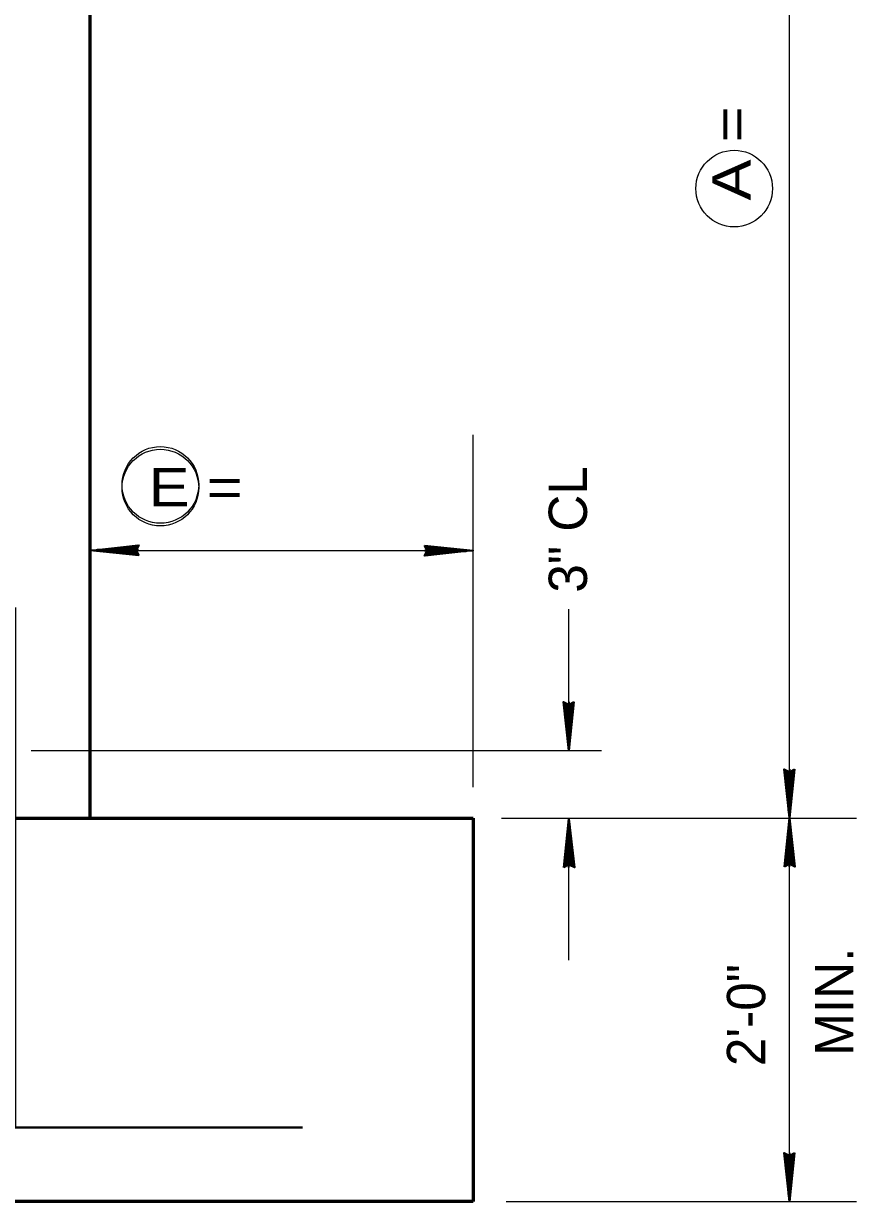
# Model space of a CAD drawing. Extents: x 4.49 to 7.69, y 0.28 to 2.27.
# Drawn here: x 6.09 to 6.2711, y 0.6015 to 0.8575 of the extents above; entities that cross this region are included whole.
import ezdxf

# ---------------------------------------------------------------- set-up
doc = ezdxf.new("R2010")
doc.units = 0
doc.header["$LTSCALE"] = 0.0033
doc.layers.add('1', color=7, linetype='Continuous', lineweight=35)

msp = doc.modelspace()

# ---------------------------------------------------------------- linework, layer by layer
at = {"layer": '1', "lineweight": 13}
for p, q in [((6.2565, 0.602333), (6.2565, 1.018083)), ((6.18775, 0.691583), (6.18775, 0.768167)), ((6.106, 0.743), (6.18775, 0.743)), ((6.208583, 0.709417), (6.208583, 0.73025)), ((6.091667, 0.6995), (6.215667, 0.6995)), ((6.193917, 0.684833), (6.271083, 0.684833)), ((6.208583, 0.653917), (6.208583, 0.67475)), ((6.140333, 0.6015), (6.182333, 0.6015)), ((6.194917, 0.6015), (6.271083, 0.6015))]:
    msp.add_line(p, q, dxfattribs=at)
at = {"layer": '1'}
for p, q in [((6.115083, 0.743), (6.1045, 0.743)), ((6.114833, 0.742167), (6.107, 0.743167)), ((6.114833, 0.742167), (6.107, 0.743)), ((6.114833, 0.742), (6.107, 0.742917)), ((6.114833, 0.742), (6.107, 0.742917)), ((6.114833, 0.742083), (6.107, 0.742917)), ((6.114833, 0.744083), (6.1075, 0.74325)), ((6.114833, 0.743917), (6.1075, 0.743167)), ((6.114833, 0.743833), (6.1075, 0.743)), ((6.114917, 0.743667), (6.107583, 0.742917)), ((6.177167, 0.743), (6.18775, 0.743)), ((6.177333, 0.742333), (6.184667, 0.743083)), ((6.177417, 0.744), (6.18525, 0.743083)), ((6.177417, 0.744), (6.18525, 0.743083)), ((6.177417, 0.743917), (6.18525, 0.743083)), ((6.177417, 0.743833), (6.18525, 0.743)), ((6.177417, 0.743833), (6.18525, 0.742833)), ((6.177417, 0.742167), (6.18475, 0.743)), ((6.177417, 0.742083), (6.18475, 0.742833)), ((6.177417, 0.741917), (6.18475, 0.74275)), ((6.2075, 0.709833), (6.208333, 0.7025)), ((6.207667, 0.709833), (6.208417, 0.7025)), ((6.20775, 0.709833), (6.208583, 0.7025)), ((6.207917, 0.709917), (6.208667, 0.702583)), ((6.209417, 0.709833), (6.208417, 0.702)), ((6.208583, 0.710083), (6.208583, 0.6995)), ((6.209417, 0.709833), (6.208583, 0.702)), ((6.209583, 0.709833), (6.208667, 0.702)), ((6.209583, 0.709833), (6.208667, 0.702)), ((6.2095, 0.709833), (6.208667, 0.702)), ((6.255417, 0.69525), (6.25625, 0.687917)), ((6.255583, 0.69525), (6.256333, 0.687917)), ((6.255667, 0.69525), (6.2565, 0.687917)), ((6.255833, 0.695333), (6.256583, 0.688)), ((6.257333, 0.69525), (6.256333, 0.687417)), ((6.2565, 0.6955), (6.2565, 0.684917)), ((6.257333, 0.69525), (6.2565, 0.687417)), ((6.2575, 0.69525), (6.256583, 0.687417)), ((6.2575, 0.69525), (6.256583, 0.687417)), ((6.257417, 0.69525), (6.256583, 0.687417)), ((6.208583, 0.674083), (6.208583, 0.684667)), ((6.2565, 0.67425), (6.2565, 0.684833)), ((6.207583, 0.674333), (6.2085, 0.682167)), ((6.207583, 0.674333), (6.2085, 0.682167)), ((6.207667, 0.674333), (6.2085, 0.682167)), ((6.20775, 0.674333), (6.208583, 0.682167)), ((6.20775, 0.674333), (6.20875, 0.682167)), ((6.20925, 0.67425), (6.2085, 0.681583)), ((6.209417, 0.674333), (6.208583, 0.681667)), ((6.2095, 0.674333), (6.20875, 0.681667)), ((6.209667, 0.674333), (6.208833, 0.681667)), ((6.2555, 0.6745), (6.256417, 0.682333)), ((6.2555, 0.6745), (6.256417, 0.682333)), ((6.255583, 0.6745), (6.256417, 0.682333)), ((6.255667, 0.6745), (6.2565, 0.682333)), ((6.255667, 0.6745), (6.256667, 0.682333)), ((6.257167, 0.674417), (6.256417, 0.68175)), ((6.257333, 0.6745), (6.2565, 0.681833)), ((6.257417, 0.6745), (6.256667, 0.681833)), ((6.257583, 0.6745), (6.25675, 0.681833)), ((6.2565, 0.612083), (6.2565, 0.6015)), ((6.255417, 0.611833), (6.25625, 0.6045)), ((6.255583, 0.611833), (6.256333, 0.6045)), ((6.255667, 0.611833), (6.2565, 0.6045)), ((6.255833, 0.611917), (6.256583, 0.604583)), ((6.257333, 0.611833), (6.256333, 0.604)), ((6.257333, 0.611833), (6.2565, 0.604)), ((6.2575, 0.611833), (6.256583, 0.604)), ((6.2575, 0.611833), (6.256583, 0.604)), ((6.257417, 0.611833), (6.256583, 0.604))]:
    msp.add_line(p, q, dxfattribs=at)
at = {"layer": '1', "lineweight": 60}
for p, q in [((6.18775, 0.684833), (6.18775, 0.6015)), ((6.18775, 0.6015), (5.854417, 0.6015))]:
    msp.add_line(p, q, dxfattribs=at)
for points in [[(5.854417, 0.684833), (5.93775, 0.684833), (5.93775, 1.018167), (6.104417, 1.018167), (6.104417, 0.684833), (6.18775, 0.684833)], [(5.93775, 0.684833), (6.00025, 0.684833), (6.00025, 0.705667), (6.041917, 0.705667), (6.041917, 0.684833), (6.104417, 0.684833)]]:
    msp.add_lwpolyline(points, dxfattribs=at)
at = {"layer": '1'}
for points in [[(6.115083, 0.741917), (6.1045, 0.743), (6.115083, 0.744167), (6.1145, 0.743)], [(6.114333, 0.742917), (6.109667, 0.742833), (6.109667, 0.742917), (6.110583, 0.742917), (6.114333, 0.742833), (6.111333, 0.74275), (6.1145, 0.742667), (6.11225, 0.742583), (6.1145, 0.7425), (6.111, 0.74275), (6.106333, 0.742917), (6.10725, 0.743167), (6.106, 0.743167), (6.114333, 0.743167), (6.111917, 0.743333), (6.1145, 0.743333), (6.109167, 0.742917), (6.1145, 0.743583)], [(6.177167, 0.744083), (6.18775, 0.743), (6.177167, 0.741833), (6.17775, 0.743)], [(6.177917, 0.743083), (6.182583, 0.743167), (6.182583, 0.743083), (6.181667, 0.743083), (6.177917, 0.743167), (6.180917, 0.74325), (6.17775, 0.743333), (6.18, 0.743417), (6.17775, 0.7435), (6.18125, 0.74325), (6.185917, 0.743083), (6.185, 0.742833), (6.18625, 0.742833), (6.177917, 0.742833), (6.180333, 0.742667), (6.17775, 0.742667), (6.183083, 0.743083), (6.17775, 0.742417)], [(6.209667, 0.710083), (6.208583, 0.6995), (6.207417, 0.710083), (6.208583, 0.7095)], [(6.208667, 0.709333), (6.20875, 0.704667), (6.208667, 0.704667), (6.208667, 0.705583), (6.20875, 0.709333), (6.208833, 0.706333), (6.208917, 0.7095), (6.209, 0.70725), (6.209083, 0.7095), (6.208833, 0.706), (6.208667, 0.701333), (6.208417, 0.70225), (6.208417, 0.701), (6.208417, 0.709333), (6.20825, 0.706917), (6.20825, 0.7095), (6.208667, 0.704167), (6.208, 0.7095)], [(6.257583, 0.6955), (6.2565, 0.684917), (6.255333, 0.6955), (6.2565, 0.694917)], [(6.256583, 0.69475), (6.256667, 0.690083), (6.256583, 0.690083), (6.256583, 0.691), (6.256667, 0.69475), (6.25675, 0.69175), (6.256833, 0.694917), (6.256917, 0.692667), (6.257, 0.694917), (6.25675, 0.691417), (6.256583, 0.68675), (6.256333, 0.687667), (6.256333, 0.686417), (6.256333, 0.69475), (6.256167, 0.692333), (6.256167, 0.694917), (6.256583, 0.689583), (6.255917, 0.694917)], [(6.2075, 0.674083), (6.208583, 0.684667), (6.20975, 0.674083), (6.208583, 0.674667)], [(6.255417, 0.67425), (6.2565, 0.684833), (6.257667, 0.67425), (6.2565, 0.674833)], [(6.2085, 0.674833), (6.208417, 0.6795), (6.2085, 0.6795), (6.2085, 0.678583), (6.208417, 0.674833), (6.208333, 0.677833), (6.20825, 0.674667), (6.208167, 0.676917), (6.208083, 0.674667), (6.208333, 0.678167), (6.2085, 0.682833), (6.20875, 0.681917), (6.20875, 0.683167), (6.20875, 0.674833), (6.208917, 0.67725), (6.208917, 0.674667), (6.2085, 0.68), (6.209167, 0.674667)], [(6.256417, 0.675), (6.256333, 0.679667), (6.256417, 0.679667), (6.256417, 0.67875), (6.256333, 0.675), (6.25625, 0.678), (6.256167, 0.674833), (6.256083, 0.677083), (6.256, 0.674833), (6.25625, 0.678333), (6.256417, 0.683), (6.256667, 0.682083), (6.256667, 0.683333), (6.256667, 0.675), (6.256833, 0.677417), (6.256833, 0.674833), (6.256417, 0.680167), (6.257083, 0.674833)], [(6.257583, 0.612083), (6.2565, 0.6015), (6.255333, 0.612083), (6.2565, 0.6115)], [(6.256583, 0.611333), (6.256667, 0.606667), (6.256583, 0.606667), (6.256583, 0.607583), (6.256667, 0.611333), (6.25675, 0.608333), (6.256833, 0.6115), (6.256917, 0.60925), (6.257, 0.6115), (6.25675, 0.608), (6.256583, 0.603333), (6.256333, 0.60425), (6.256333, 0.603), (6.256333, 0.611333), (6.256167, 0.608917), (6.256167, 0.6115), (6.256583, 0.606167), (6.255917, 0.6115)]]:
    msp.add_lwpolyline(points, close=True, dxfattribs=at)
for points in [[(6.114333, 0.742917), (6.11475, 0.742167), (6.1145, 0.742417), (6.114333, 0.74275), (6.114083, 0.742667), (6.11425, 0.742333), (6.114417, 0.743083), (6.114583, 0.743583), (6.114833, 0.744)], [(6.177917, 0.743083), (6.1775, 0.743833), (6.17775, 0.743583), (6.177917, 0.74325), (6.178167, 0.743333), (6.178, 0.743667), (6.177833, 0.742917), (6.177667, 0.742417), (6.177417, 0.742)], [(6.208667, 0.709333), (6.209417, 0.70975), (6.209167, 0.7095), (6.208833, 0.709333), (6.208917, 0.709083), (6.20925, 0.70925), (6.2085, 0.709417), (6.208, 0.709583), (6.207583, 0.709833)], [(6.256583, 0.69475), (6.257333, 0.695167), (6.257083, 0.694917), (6.25675, 0.69475), (6.256833, 0.6945), (6.257167, 0.694667), (6.256417, 0.694833), (6.255917, 0.695), (6.2555, 0.69525)], [(6.2085, 0.674833), (6.20775, 0.674417), (6.208, 0.674667), (6.208333, 0.674833), (6.20825, 0.675083), (6.207917, 0.674917), (6.208667, 0.67475), (6.209167, 0.674583), (6.209583, 0.674333)], [(6.256417, 0.675), (6.255667, 0.674583), (6.255917, 0.674833), (6.25625, 0.675), (6.256167, 0.67525), (6.255833, 0.675083), (6.256583, 0.674917), (6.257083, 0.67475), (6.2575, 0.6745)], [(6.256583, 0.611333), (6.257333, 0.61175), (6.257083, 0.6115), (6.25675, 0.611333), (6.256833, 0.611083), (6.257167, 0.61125), (6.256417, 0.611417), (6.255917, 0.611583), (6.2555, 0.611833)]]:
    msp.add_lwpolyline(points, dxfattribs=at)
at = {"layer": '1', "lineweight": 40}
msp.add_lwpolyline([(6.088167, 0.730583), (6.088167, 0.617583), (6.150667, 0.617583)], dxfattribs=at)
at = {"layer": '1', "lineweight": 13}
for centre in [(6.2445, 0.821667), (6.11975, 0.75725), (6.11975, 0.756667)]:
    msp.add_circle(centre, 0.008333, dxfattribs=at)

# ---------------------------------------------------------------- texts
at = {"layer": '1', "width": 1.2}
msp.add_text('A =      ', height=0.008334, rotation=90, dxfattribs=at).set_placement((6.248083, 0.819083))
msp.add_text('E =      ', height=0.008334, dxfattribs=at).set_placement((6.117167, 0.752583))
at = {"layer": '1'}
for s, height, p in [('3" CL', 0.008334, (6.2125, 0.733833)), ('MIN.', 0.008334, (6.270417, 0.633167)), ('2\'-0"', 0.008333, (6.25125, 0.630917))]:
    msp.add_text(s, height=height, rotation=90, dxfattribs=at).set_placement(p)

doc.saveas('drawing.dxf')
